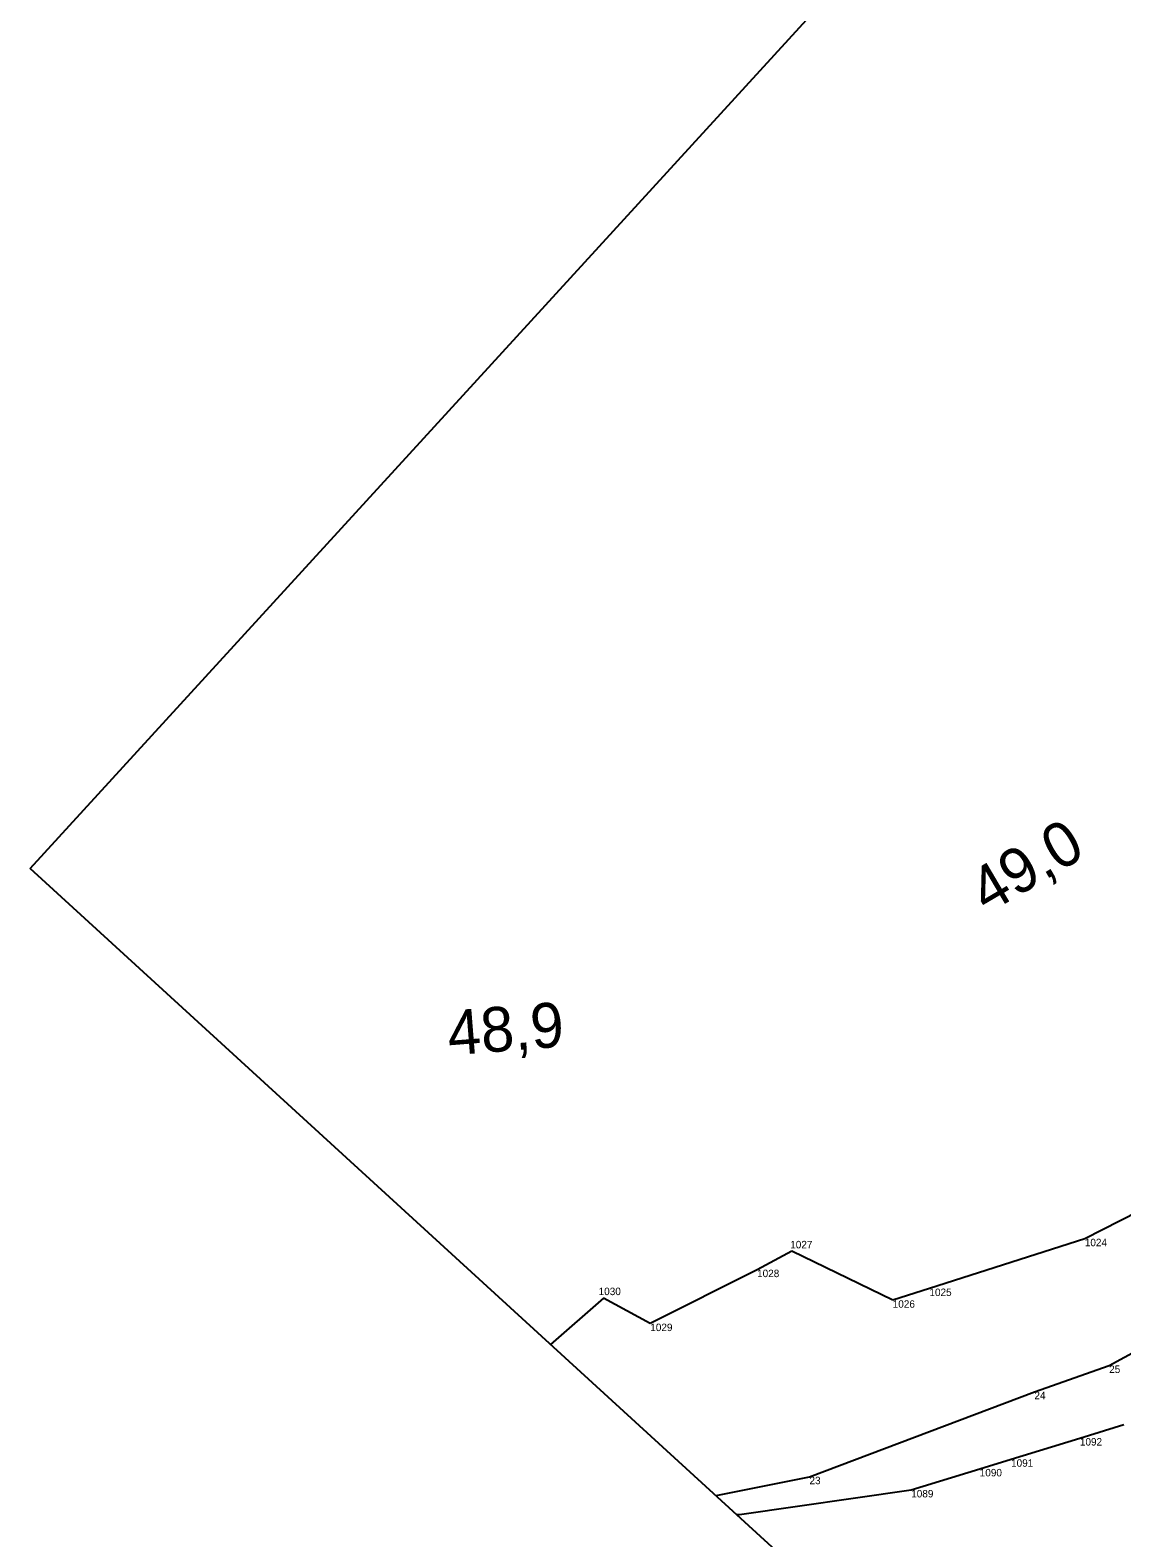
# Model space of a CAD drawing. Extents: x -678683 to -677755, y -1006946 to -1005971.
# Drawn here: x -678683 to -678536.7, y -1006835.5 to -1006633.5 of the extents above; entities that cross this region are included whole.
import ezdxf

# ---------------------------------------------------------------- set-up
doc = ezdxf.new("R2010")
doc.units = 0
for name, color, linetype in [('rozpiska - Lichá Tisk', 7, 'Continuous'), ('SSZT nové - lomové body', 7, 'Continuous'), ('SSZT_nové', 7, 'Continuous'), ('SŽDC', 7, 'Continuous'), ('SŽDC - body', 7, 'Continuous'), ('Vrstva 7', 7, 'Continuous')]:
    doc.layers.add(name, color=color, linetype=linetype)

msp = doc.modelspace()

# ---------------------------------------------------------------- linework, layer by layer
at = {"layer": 'rozpiska - Lichá Tisk'}
for p, q in [((-678682.98, -1006745.8), (-678541.24, -1006590.84)), ((-678463.83, -1006946.26), (-678682.98, -1006745.8))]:
    msp.add_line(p, q, dxfattribs=at)
at = {"layer": 'SSZT nové - lomové body'}
for p, q in [((-678538.41, -1006812.42), (-678538.41, -1006812.42)), ((-678548.42, -1006815.94), (-678548.42, -1006815.94)), ((-678578.56, -1006827.33), (-678578.56, -1006827.33))]:
    msp.add_line(p, q, dxfattribs=at)
at = {"layer": 'SSZT_nové'}
msp.add_lwpolyline([(-678591.08, -1006829.86), (-678578.56, -1006827.33), (-678548.42, -1006815.94), (-678538.41, -1006812.42), (-678518.43, -1006801.56), (-678506.62, -1006791.94), (-678506.62, -1006791.94)], dxfattribs=at)
at = {"layer": 'SŽDC'}
for p, q in [((-678513.57, -1006781.17), (-678541.67, -1006795.44)), ((-678541.67, -1006795.44), (-678562.49, -1006802.11)), ((-678580.93, -1006797.11), (-678585.58, -1006799.58)), ((-678567.41, -1006803.68), (-678580.93, -1006797.11)), ((-678585.58, -1006799.58), (-678599.89, -1006806.81)), ((-678606.18, -1006803.39), (-678613.24, -1006809.59)), ((-678599.89, -1006806.81), (-678606.18, -1006803.39)), ((-678562.49, -1006802.11), (-678567.41, -1006803.68)), ((-678551.55, -1006824.99), (-678542.33, -1006822.15)), ((-678542.33, -1006822.15), (-678536.44, -1006820.34)), ((-678555.75, -1006826.28), (-678551.55, -1006824.99)), ((-678564.93, -1006829.1), (-678555.75, -1006826.28)), ((-678587.94, -1006832.39), (-678564.93, -1006829.1)), ((-678588.31, -1006832.39), (-678587.94, -1006832.39))]:
    msp.add_line(p, q, dxfattribs=at)
at = {"layer": 'SŽDC - body'}
for p, q in [((-678541.67, -1006795.44), (-678541.67, -1006795.44)), ((-678580.93, -1006797.11), (-678580.93, -1006797.11)), ((-678585.58, -1006799.58), (-678585.58, -1006799.58)), ((-678606.18, -1006803.39), (-678606.18, -1006803.39)), ((-678567.41, -1006803.68), (-678567.41, -1006803.68)), ((-678562.49, -1006802.11), (-678562.49, -1006802.11)), ((-678599.89, -1006806.81), (-678599.89, -1006806.81)), ((-678542.33, -1006822.15), (-678542.33, -1006822.15)), ((-678551.55, -1006824.99), (-678551.55, -1006824.99)), ((-678555.75, -1006826.28), (-678555.75, -1006826.28)), ((-678564.93, -1006829.1), (-678564.93, -1006829.1)), ((-678587.94, -1006832.39), (-678587.94, -1006832.39))]:
    msp.add_line(p, q, dxfattribs=at)

# ---------------------------------------------------------------- texts
at = {"layer": 'SSZT nové - lomové body'}
for s, p in [('25', (-678538.41, -1006813.42)), ('24', (-678548.42, -1006816.94)), ('23', (-678578.56, -1006828.33))]:
    msp.add_text(s, height=1, dxfattribs=at).set_placement(p)
at = {"layer": 'SŽDC - body'}
for s, p in [('1027', (-678581.14, -1006796.72)), ('1024', (-678541.67, -1006796.44)), ('1028', (-678585.58, -1006800.58)), ('1030', (-678606.81, -1006802.99)), ('1026', (-678567.41, -1006804.68)), ('1025', (-678562.49, -1006803.11)), ('1029', (-678599.89, -1006807.81)), ('1092', (-678542.33, -1006823.15)), ('1091', (-678551.55, -1006825.99)), ('1090', (-678555.75, -1006827.28)), ('1089', (-678564.93, -1006830.1))]:
    msp.add_text(s, height=1, dxfattribs=at).set_placement(p)
at = {"layer": 'Vrstva 7'}
for s, rotation, p in [('49,0', 30.5229, (-678554.77, -1006751.98)), ('48,9', 4.5291, (-678626.84, -1006770.88))]:
    msp.add_text(s, height=6, rotation=rotation, dxfattribs=at).set_placement(p)

doc.saveas('drawing.dxf')
